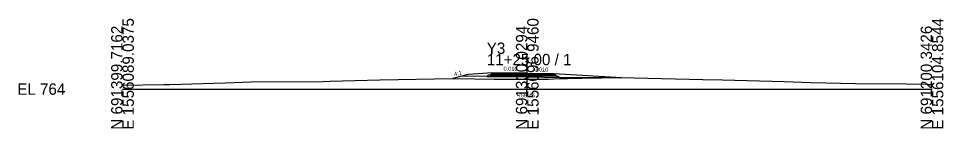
# Model space of a CAD drawing. Extents: x -26 to 203, y -10 to 1517.
# Drawn here: x -25.7 to 202.8, y 1490.3 to 1517.4 of the extents above; entities that cross this region are included whole.
import ezdxf

# ---------------------------------------------------------------- set-up
doc = ezdxf.new("R2010")
doc.units = 0
for name, color, linetype in [('Exist Cross Section Cell', 7, 'Continuous'), ('Exist XS Center Line Elevation Label', 7, 'Continuous'), ('Exist XS Ground Line', 7, 'Continuous'), ('Prop CMT Pvmt Course 1', 7, 'Continuous'), ('Prop CMT Pvmt Course 2', 7, 'Continuous'), ('Prop CMT Pvmt Course 3', 7, 'Continuous'), ('Prop CMT Pvmt Surface', 7, 'Continuous'), ('Prop CMT Shld Paved Course 1', 7, 'Continuous'), ('Prop CMT Shld Paved Course 2', 7, 'Continuous'), ('Prop CMT Shld Paved Course 3', 7, 'Continuous'), ('Prop CMT Slope Grass', 7, 'Continuous'), ('Prop CMT Subgrade Earthwork', 7, 'Continuous'), ('Prop XS Earthwork Shape', 7, 'Continuous'), ('Prop XS SE Text', 7, 'Continuous'), ('Prop XS Side Slope Text', 7, 'Continuous')]:
    doc.layers.add(name, color=color, linetype=linetype)

msp = doc.modelspace()

# ---------------------------------------------------------------- linework, layer by layer
at = {"layer": 'Exist Cross Section Cell'}
for p, q in [((100, 1500), (100, 1508.67)), ((0, 1500), (100, 1500)), ((100, 1500), (200, 1500))]:
    msp.add_line(p, q, dxfattribs=at)
at = {"layer": 'Exist XS Ground Line'}
msp.add_lwpolyline([(0, 1500.98), (10.13, 1501.13), (11.68, 1501.14), (25.37, 1501.56), (31.76, 1501.76), (49.57, 1501.91), (51.27, 1501.92), (57.37, 1502.08), (63.58, 1502.24), (81.65, 1502.63), (82.15, 1502.63), (91.86, 1502.44), (100, 1502.46), (105.25, 1502.47), (106.46, 1502.49), (113.37, 1502.66), (123.32, 1502.89), (126.44, 1502.81), (143.39, 1502.37), (148.23, 1502.29), (163.45, 1501.87), (170.1, 1501.61), (181.13, 1501.39), (193.63, 1501.3), (199.01, 1501.23), (199.15, 1501.1), (200, 1501.12)], dxfattribs=at)
at = {"layer": 'Prop CMT Pvmt Course 1'}
msp.add_lwpolyline([(100, 1503.71), (100, 1503.96)], dxfattribs=at)
msp.add_lwpolyline([(100, 1503.71), (100, 1503.96)], dxfattribs=at)
at = {"layer": 'Prop CMT Pvmt Course 2'}
msp.add_lwpolyline([(100, 1503.37), (100, 1503.71)], dxfattribs=at)
msp.add_lwpolyline([(100, 1503.37), (100, 1503.71)], dxfattribs=at)
at = {"layer": 'Prop CMT Pvmt Course 3'}
msp.add_lwpolyline([(100, 1503.04), (100, 1503.37)], dxfattribs=at)
msp.add_lwpolyline([(100, 1503.04), (100, 1503.37)], dxfattribs=at)
at = {"layer": 'Prop CMT Pvmt Surface'}
for points in [[(100, 1503.96), (91.38, 1504.04)], [(100, 1503.96), (106.53, 1503.83)]]:
    msp.add_lwpolyline(points, dxfattribs=at)
at = {"layer": 'Prop CMT Shld Paved Course 1'}
for points in [[(100, 1503.96), (91.38, 1504.04), (91.14, 1503.79)], [(91.14, 1503.79), (100, 1503.71)], [(100, 1503.96), (106.53, 1503.83), (106.79, 1503.57)], [(106.79, 1503.57), (100, 1503.71)]]:
    msp.add_lwpolyline(points, dxfattribs=at)
at = {"layer": 'Prop CMT Shld Paved Course 2'}
for points in [[(100, 1503.71), (91.14, 1503.79), (90.81, 1503.46)], [(90.81, 1503.46), (100, 1503.37)], [(100, 1503.71), (106.79, 1503.57), (107.13, 1503.23)], [(107.13, 1503.23), (100, 1503.37)]]:
    msp.add_lwpolyline(points, dxfattribs=at)
at = {"layer": 'Prop CMT Shld Paved Course 3'}
for points in [[(100, 1503.37), (90.81, 1503.46), (90.32, 1503.47), (89.99, 1503.14)], [(89.99, 1503.14), (100, 1503.04)], [(100, 1503.37), (107.13, 1503.23), (107.63, 1503.22), (107.97, 1502.88)], [(107.97, 1502.88), (100, 1503.04)]]:
    msp.add_lwpolyline(points, dxfattribs=at)
at = {"layer": 'Prop CMT Slope Grass'}
for points in [[(91.38, 1504.04), (85.38, 1503.56), (81.65, 1502.63)], [(106.53, 1503.83), (123.32, 1502.89)]]:
    msp.add_lwpolyline(points, dxfattribs=at)
at = {"layer": 'Prop CMT Subgrade Earthwork'}
msp.add_line((114.95, 1502.74), (123.32, 1502.89), dxfattribs=at)
for points in [[(89.99, 1503.14), (83.94, 1503.2)], [(100, 1503.04), (89.99, 1503.14)], [(100, 1503.04), (107.97, 1502.88)], [(107.97, 1502.88), (114.95, 1502.74)]]:
    msp.add_lwpolyline(points, dxfattribs=at)
at = {"layer": 'Prop XS Earthwork Shape'}
msp.add_lwpolyline([(82.15, 1502.63), (91.86, 1502.44), (100, 1502.46), (105.25, 1502.47), (106.46, 1502.49), (113.37, 1502.66), (123.32, 1502.89), (114.95, 1502.74), (107.97, 1502.88), (100, 1503.04), (89.99, 1503.14), (83.94, 1503.2), (81.65, 1502.63)], close=True, dxfattribs=at)

# ---------------------------------------------------------------- texts
at = {"layer": 'Exist Cross Section Cell'}
for s, p in [('N 691399.7162', (0, 1490)), ('E 1556089.0375', (2.8, 1490)), ('N 691300.0294', (100, 1490)), ('E 1556096.9460', (102.8, 1490)), ('N 691200.3426', (200, 1490)), ('E 1556104.8544', (202.8, 1490))]:
    msp.add_text(s, height=2.8, rotation=90, dxfattribs=at).set_placement(p)
for s, p in [('Y3', (90, 1508.67)), ('11+25.00 / 1', (90, 1505.87)), ('EL 764', (-26, 1498.6))]:
    msp.add_text(s, height=2.8, dxfattribs=at).set_placement(p)
at = {"layer": 'Exist XS Center Line Elevation Label'}
msp.add_text('766.46', height=1, dxfattribs=at).set_placement((97.68, 1497.96))
at = {"layer": 'Prop XS SE Text'}
for rotation, p in [(359.4271, (94.14, 1504.52)), (358.8542, (101.74, 1504.36))]:
    msp.add_text('0.010', height=1, rotation=rotation, dxfattribs=at).set_placement(p)
at = {"layer": 'Prop XS Side Slope Text'}
msp.add_text('4:1', height=1, rotation=14.0362, dxfattribs=at).set_placement((82.06, 1503.15))

doc.saveas('drawing.dxf')
